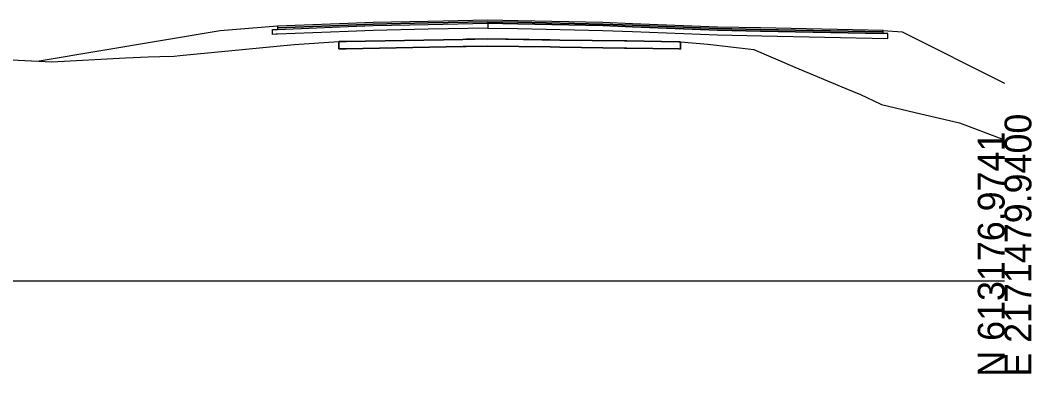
# Model space of a CAD drawing. Extents: x -26 to 1303, y -3010 to 12038.
# Drawn here: x 197.1 to 302.8, y 3990.3 to 4027.2 of the extents above; entities that cross this region are included whole.
import ezdxf

# ---------------------------------------------------------------- set-up
doc = ezdxf.new("R2010")
doc.units = 0
for name, color, linetype in [('RD_GPK_XS_Cell', 7, 'Continuous'), ('RD_XS_Base', 7, 'Continuous'), ('RD_XS_ExGround', 7, 'Continuous'), ('RD_XS_ExPaveRet', 7, 'Continuous'), ('RD_XS_Greenside', 7, 'Continuous'), ('RD_XS_Pave', 7, 'Continuous'), ('RD_XS_PaveOvlay_CP', 7, 'Continuous'), ('RD_XS_TieSlope', 7, 'Continuous')]:
    doc.layers.add(name, color=color, linetype=linetype)

msp = doc.modelspace()

# ---------------------------------------------------------------- linework, layer by layer
at = {"layer": 'RD_GPK_XS_Cell'}
msp.add_line((150, 4000), (300, 4000), dxfattribs=at)
at = {"layer": 'RD_XS_Base'}
for p, q in [((239.76, 4026.8), (246, 4026.93)), ((246, 4027.05), (246, 4027.09)), ((246, 4027.09), (246, 4026.92)), ((246, 4026.93), (246, 4027.05)), ((246, 4026.93), (246, 4026.93)), ((249.12, 4026.87), (246, 4026.93)), ((246, 4026.93), (246, 4026.93)), ((246, 4026.93), (246, 4026.8)), ((246, 4026.92), (246, 4026.43)), ((258, 4026.69), (249.12, 4026.87)), ((223.5, 4026.27), (223.87, 4026.28)), ((223.5, 4026.14), (223.5, 4026.27)), ((223.5, 4025.77), (223.5, 4026.14)), ((223.87, 4026.28), (224, 4026.29)), ((224, 4025.79), (223.87, 4025.78)), ((224, 4026.29), (231.4, 4026.58)), ((231.4, 4026.08), (224, 4025.79)), ((231.4, 4026.58), (234, 4026.69)), ((234, 4026.19), (231.4, 4026.08)), ((234, 4026.69), (239.76, 4026.8)), ((239.76, 4026.3), (234, 4026.19)), ((246, 4026.43), (239.76, 4026.3)), ((246, 4026.8), (246, 4026.43)), ((246, 4026.43), (249.12, 4026.37)), ((249.12, 4026.37), (258, 4026.19)), ((261.12, 4026.56), (258, 4026.69)), ((258, 4026.19), (261.12, 4026.06)), ((270, 4026.21), (261.12, 4026.56)), ((261.12, 4026.06), (270, 4025.71)), ((274.5, 4026.12), (270, 4026.21)), ((287.3, 4025.86), (274.5, 4026.12)), ((287.43, 4025.86), (287.3, 4025.86)), ((287.8, 4025.85), (287.43, 4025.86)), ((287.8, 4025.72), (287.8, 4025.85)), ((223.87, 4025.78), (223.5, 4025.77)), ((270, 4025.71), (274.63, 4025.62)), ((274.63, 4025.62), (287.8, 4025.35)), ((287.8, 4025.35), (287.8, 4025.72))]:
    msp.add_line(p, q, dxfattribs=at)
at = {"layer": 'RD_XS_ExGround'}
msp.add_lwpolyline([(189.14, 4023.47), (200.44, 4022.91), (208.11, 4023.31), (210.49, 4023.41), (211.72, 4023.45), (213.2, 4023.5), (213.81, 4023.56), (225.75, 4024.72), (230.43, 4025.01), (243.37, 4025.25), (245.92, 4025.29), (253.51, 4025.18), (260.53, 4025.08), (266.14, 4024.99), (268.98, 4024.73), (273.78, 4024.2), (278.06, 4022.36), (283.41, 4020.11), (284.95, 4019.5), (287, 4018.52), (287.12, 4018.45), (290.65, 4017.62), (295.29, 4016.51), (299.7, 4014.87), (300, 4014.77)], dxfattribs=at)
at = {"layer": 'RD_XS_ExPaveRet'}
for p, q in [((243.37, 4025.25), (231.19, 4025.02)), ((243.71, 4025.26), (243.37, 4025.25)), ((245.92, 4025.29), (243.71, 4025.26)), ((266.14, 4024.99), (265.95, 4025))]:
    msp.add_line(p, q, dxfattribs=at)
for points in [[(265.95, 4025), (266.14, 4024.99), (266.14, 4024.94), (266.14, 4024.24), (265.95, 4024.25), (260.53, 4024.33), (260.29, 4024.34), (253.51, 4024.43), (252.5, 4024.45), (245.92, 4024.54), (243.71, 4024.51), (243.37, 4024.5), (231.19, 4024.27), (230.43, 4024.26), (230.43, 4024.95), (230.43, 4025.01), (231.19, 4025.02), (243.37, 4025.25), (243.71, 4025.26), (245.92, 4025.29), (252.5, 4025.2), (253.51, 4025.18), (260.29, 4025.09), (260.53, 4025.08), (265.95, 4025)], [(231.19, 4025.02), (230.43, 4025.01), (230.43, 4024.95), (230.43, 4024.26), (231.19, 4024.27), (243.37, 4024.5), (243.71, 4024.51), (245.92, 4024.54), (252.5, 4024.45), (253.51, 4024.43), (260.29, 4024.34), (260.53, 4024.33), (265.95, 4024.25), (266.14, 4024.24), (266.14, 4024.94), (266.14, 4024.99)], [(253.51, 4025.18), (252.5, 4025.2), (245.92, 4025.29)], [(265.95, 4025), (260.53, 4025.08), (260.29, 4025.09), (253.51, 4025.18)]]:
    msp.add_lwpolyline(points, dxfattribs=at)
at = {"layer": 'RD_XS_Greenside'}
for p, q in [((218, 4026.13), (199.11, 4022.98)), ((289.3, 4026.02), (300, 4020.67))]:
    msp.add_line(p, q, dxfattribs=at)
at = {"layer": 'RD_XS_Pave'}
for p, q in [((231.4, 4026.9), (224, 4026.61)), ((234, 4027.01), (231.4, 4026.9)), ((234, 4026.85), (231.4, 4026.74)), ((231.4, 4026.74), (234, 4026.85)), ((239.76, 4027.12), (234, 4027.01)), ((239.76, 4026.96), (234, 4026.85)), ((234, 4026.85), (239.76, 4026.96)), ((246, 4027.25), (239.76, 4027.12)), ((246, 4027.09), (239.76, 4026.96)), ((239.76, 4026.96), (246, 4027.09)), ((239.76, 4026.8), (246, 4026.93)), ((249.12, 4027.18), (246, 4027.25)), ((246, 4027.05), (246, 4027.09)), ((246, 4027.09), (249.12, 4027.03)), ((249.12, 4027.03), (246, 4027.09)), ((246, 4027.09), (246, 4027.09)), ((246, 4027.09), (246, 4027.09)), ((246, 4027.09), (246, 4027.05)), ((246, 4026.93), (246, 4027.05)), ((246, 4027.05), (246, 4026.93)), ((246, 4026.93), (246, 4026.93)), ((246, 4026.93), (246, 4026.93)), ((246, 4026.93), (249.12, 4026.87)), ((258, 4027.01), (249.12, 4027.18)), ((249.12, 4027.03), (258, 4026.85)), ((258, 4026.85), (249.12, 4027.03)), ((249.12, 4026.87), (258, 4026.69)), ((261.12, 4026.88), (258, 4027.01)), ((258, 4026.85), (261.12, 4026.72)), ((261.12, 4026.72), (258, 4026.85)), ((270, 4026.53), (261.12, 4026.88)), ((231.4, 4026.74), (224, 4026.45)), ((224, 4026.45), (231.4, 4026.74)), ((224, 4026.61), (224, 4026.57)), ((224, 4026.29), (231.4, 4026.58)), ((224, 4026.57), (224, 4026.45)), ((224, 4026.45), (224, 4026.41)), ((224, 4026.41), (224, 4026.29)), ((231.4, 4026.58), (234, 4026.69)), ((234, 4026.69), (239.76, 4026.8)), ((258, 4026.69), (261.12, 4026.56)), ((261.12, 4026.72), (270, 4026.37)), ((270, 4026.37), (261.12, 4026.72)), ((261.12, 4026.56), (270, 4026.21)), ((274.5, 4026.44), (270, 4026.53)), ((270, 4026.37), (274.5, 4026.28)), ((274.5, 4026.28), (270, 4026.37)), ((270, 4026.21), (274.5, 4026.12)), ((287.3, 4026.18), (274.5, 4026.44)), ((274.5, 4026.28), (287.3, 4026.02)), ((287.3, 4026.02), (274.5, 4026.28)), ((274.5, 4026.12), (287.3, 4025.86)), ((287.3, 4026.14), (287.3, 4026.18)), ((287.3, 4026.02), (287.3, 4026.14)), ((287.3, 4025.98), (287.3, 4026.02)), ((287.3, 4025.86), (287.3, 4025.98))]:
    msp.add_line(p, q, dxfattribs=at)
at = {"layer": 'RD_XS_PaveOvlay_CP'}
for p, q in [((231.4, 4026.9), (224, 4026.61)), ((234, 4027.01), (231.4, 4026.9)), ((239.76, 4027.12), (234, 4027.01)), ((246, 4027.25), (239.76, 4027.12)), ((249.12, 4027.18), (246, 4027.25)), ((258, 4027.01), (249.12, 4027.18)), ((261.12, 4026.88), (258, 4027.01)), ((270, 4026.53), (261.12, 4026.88)), ((274.5, 4026.44), (270, 4026.53)), ((287.3, 4026.18), (274.5, 4026.44))]:
    msp.add_line(p, q, dxfattribs=at)
at = {"layer": 'RD_XS_TieSlope'}
for p, q in [((224, 4026.61), (218, 4026.13)), ((287.3, 4026.18), (289.3, 4026.02))]:
    msp.add_line(p, q, dxfattribs=at)

# ---------------------------------------------------------------- texts
at = {"layer": 'RD_GPK_XS_Cell'}
for s, p in [('E 2171479.9400', (302.8, 3990)), ('N 613176.9741', (300, 3990))]:
    msp.add_text(s, height=2.8, rotation=90, dxfattribs=at).set_placement(p)

doc.saveas('drawing.dxf')
